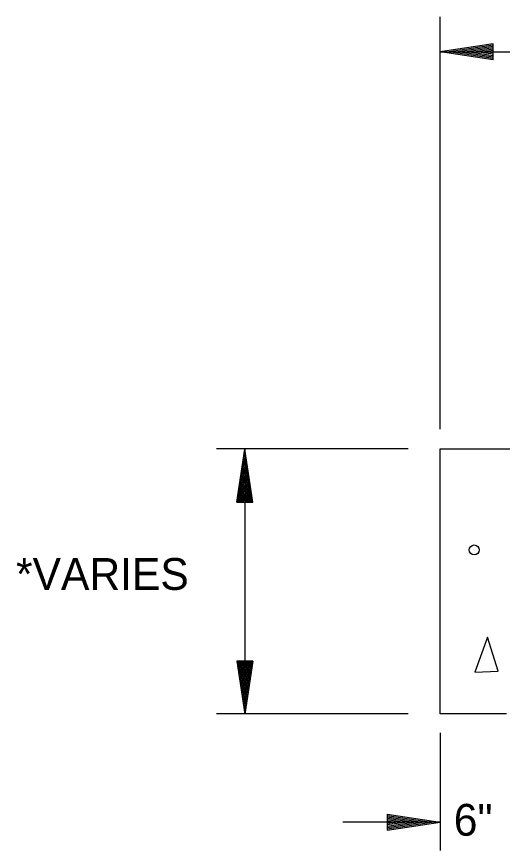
# Model space of a CAD drawing. Extents: x -149 to 1228740, y -106 to 152440.
# Drawn here: x -138.95 to -129.7, y 50.38 to 66.28 of the extents above; entities that cross this region are included whole.
import ezdxf

# ---------------------------------------------------------------- set-up
doc = ezdxf.new("R2010")
doc.units = 0
for name, color, linetype in [('R_Annotation', 7, 'Continuous'), ('R_Dimension', 7, 'Continuous'), ('R_Proposed Road', 7, 'Continuous')]:
    doc.layers.add(name, color=color, linetype=linetype)

msp = doc.modelspace()

# ---------------------------------------------------------------- linework, layer by layer
at = {"layer": 'R_Dimension'}
for p, q in [((-130.883, 58.412), (-130.883, 66.276)), ((-129.871, 65.759), (-130.882, 65.607)), ((-129.871, 65.734), (-130.712, 65.607)), ((-129.871, 65.708), (-130.54, 65.607)), ((-129.871, 65.683), (-130.371, 65.607)), ((-129.871, 65.658), (-130.199, 65.607)), ((-129.871, 65.456), (-129.871, 65.759)), ((-130.883, 65.608), (-85.402, 65.608)), ((-129.871, 65.456), (-130.882, 65.607)), ((-129.871, 65.481), (-130.712, 65.607)), ((-129.871, 65.506), (-130.54, 65.607)), ((-129.871, 65.532), (-130.371, 65.607)), ((-129.871, 65.559), (-130.199, 65.607)), ((-129.871, 65.633), (-130.03, 65.607)), ((-129.871, 65.585), (-130.03, 65.607)), ((-131.493, 58.034), (-135.145, 58.034)), ((-134.758, 57.022), (-134.606, 58.032)), ((-134.606, 58.034), (-134.606, 52.98)), ((-134.454, 57.022), (-134.606, 58.032)), ((-134.732, 57.022), (-134.606, 57.865)), ((-134.48, 57.022), (-134.606, 57.865)), ((-134.705, 57.022), (-134.606, 57.691)), ((-134.505, 57.022), (-134.606, 57.691)), ((-134.679, 57.022), (-134.606, 57.522)), ((-134.53, 57.022), (-134.606, 57.522)), ((-134.654, 57.022), (-134.606, 57.35)), ((-134.555, 57.022), (-134.606, 57.35)), ((-134.629, 57.022), (-134.606, 57.183)), ((-134.581, 57.022), (-134.606, 57.183)), ((-134.758, 57.022), (-134.454, 57.022)), ((-134.758, 53.989), (-134.606, 52.979)), ((-134.454, 53.989), (-134.758, 53.989)), ((-134.732, 53.989), (-134.606, 53.148)), ((-134.705, 53.989), (-134.606, 53.322)), ((-134.679, 53.989), (-134.606, 53.492)), ((-134.654, 53.989), (-134.606, 53.661)), ((-134.629, 53.989), (-134.606, 53.83)), ((-134.454, 53.989), (-134.606, 52.979)), ((-134.555, 53.989), (-134.606, 53.661)), ((-134.505, 53.989), (-134.606, 53.322)), ((-134.48, 53.989), (-134.606, 53.148)), ((-134.53, 53.989), (-134.606, 53.492)), ((-134.581, 53.989), (-134.606, 53.83)), ((-131.493, 52.98), (-135.145, 52.98)), ((-130.883, 52.623), (-130.883, 50.38)), ((-131.892, 51.071), (-130.882, 50.919)), ((-131.892, 51.071), (-131.892, 50.768)), ((-131.892, 51.046), (-131.051, 50.919)), ((-130.883, 50.92), (-132.738, 50.92)), ((-131.892, 51.021), (-131.225, 50.919)), ((-131.892, 50.995), (-131.392, 50.919)), ((-131.892, 50.97), (-131.564, 50.919)), ((-131.892, 50.945), (-131.733, 50.919)), ((-131.892, 50.768), (-130.882, 50.919)), ((-131.892, 50.871), (-131.564, 50.919)), ((-131.892, 50.818), (-131.225, 50.919)), ((-131.892, 50.793), (-131.051, 50.919)), ((-131.892, 50.844), (-131.392, 50.919)), ((-131.892, 50.897), (-131.733, 50.919))]:
    msp.add_line(p, q, dxfattribs=at)
at = {"layer": 'R_Proposed Road'}
for p, q in [((-130.883, 58.034), (-89.192, 58.034)), ((-130.883, 52.98), (-130.883, 58.034)), ((-129.62, 52.98), (-130.883, 52.98))]:
    msp.add_line(p, q, dxfattribs=at)
msp.add_lwpolyline([(-129.98, 54.447), (-130.225, 53.775), (-129.78, 53.795), (-129.98, 54.447)], dxfattribs=at)
msp.add_circle((-130.235, 56.108), 0.0947, dxfattribs=at)

# ---------------------------------------------------------------- texts
at = {"layer": 'R_Annotation'}
for s, p in [('*VARIES', (-138.962, 55.347)), ('6"', (-130.624, 50.659))]:
    msp.add_text(s, height=0.6065, dxfattribs=at).set_placement(p)

doc.saveas('drawing.dxf')
